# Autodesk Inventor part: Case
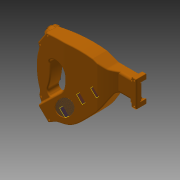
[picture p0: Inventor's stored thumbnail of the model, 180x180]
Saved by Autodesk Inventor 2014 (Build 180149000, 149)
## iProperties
Created: 2008-06
Part Number: Case
Document SubType Name: Modeling
Designer: tangg
Density: 1.06 g/cm^3
Mass: 76.5176 g
Surface Area: 2978.07 cm^2
Volume: 72.1864 cm^3
Stock Number: Case
Material: ABS Plastic
Appearance: Orange
Author: tangg
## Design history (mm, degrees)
sketch "Sketch1"
  geometry: L1 (127.385, 15.24)-(71.466, 15.24); L2 (143.279, 24.13)-(143.279, -44.45); L3 (127.385, -35.56)-(92.277, -35.56); L4 (81.416, -41.677)-(60.325, -76.472); L5 (-66.363, -173.038)-(-82.55, -182.562); L6 (-82.55, -182.562)-(-114.541, -151.565); L7 (47.484, -46.179)-(34.222, -59.441) reference; L8 (47.484, -46.179)-(34.222, -59.441) reference; L9 (34.222, -59.441)-(0, -93.663); L10 (142.009, 25.4)-(133.735, 25.4); L11 (130.56, 22.225)-(130.56, 18.415); L12 (142.009, -45.72)-(133.735, -45.72); L13 (130.56, -42.545)-(130.56, -38.735); L14 (67.2, 15.978)-(37.285, 26.647); L15 (-38.763, -45.049)-(-38.763, -86.032); L16 (-76.383, -122.164)-(-38.763, -86.032); L17 (-122.604, -21.78)-(-95.903, 16.854); A1 r 3.175 centre (133.735, 22.225) between (133.735, 25.4) and (130.56, 22.225); A2 r 3.175 centre (127.385, 18.415) between (127.385, 15.24) and (130.56, 18.415); A3 r 3.175 centre (133.735, -42.545) between (130.56, -42.545) and (133.735, -45.72); A4 r 1.27 centre (142.009, 24.13) between (143.279, 24.13) and (142.009, 25.4); A5 r 1.27 centre (142.009, -44.45) between (142.009, -45.72) and (143.279, -44.45); A6 r 12.7 centre (92.277, -48.26) between (92.277, -35.56) and (81.416, -41.677); A7 r 12.7 centre (71.466, 27.94) between (67.2, 15.978) and (71.466, 15.24); A8 r 3.175 centre (127.385, -38.735) between (130.56, -38.735) and (127.385, -35.56); A9 r 29.205 centre (-63.108, -61.181) between (-38.763, -45.049) and (-81.793, -38.735); 28 further points
  constraints: 34 end point, 18 point on circle, 16 point on line, 16 tangent, 9 centre point, 4 equal radius, 2 horizontal, 40 other
  dimensions: "d25" = 3.175 radius of A1; "d26" = 1.27 radius of A4; "d27" = 12.7 radius of A6; "d137" = 15.24 distance from line of point (0, 0) L1; "d138" = 35.56 distance from line of point (0, 0) L3; "d139" = 25.4 distance from line of point (0, 0) L10; "d140" = 45.72 distance from line of point (0, 0) L12; "d141" = 3.175 radius of A8
extrude "Extrusion8" new body sketch "Sketch1" distance "d71" = 38.1; taper "d72" = 0 deg
feature "Sculpt2"
fillet "Fillet9" dims "d73" = 6.35
sketch "Sketch11"
  geometry: L1 (-127.385, 15.24)-(-71.466, 15.24) reference; L2 (-67.2, 15.978)-(-37.285, 26.647) reference; L3 (114.541, -151.565)-(82.55, -182.562) reference; L4 (82.55, -182.562)-(66.363, -173.038) reference; L5 (-60.325, -76.472)-(-81.416, -41.677) reference; L6 (-92.277, -35.56)-(-127.385, -35.56) reference; L7 (-130.56, -38.735)-(-130.56, -42.545) reference; L8 (-133.735, -45.72)-(-142.009, -45.72) reference; L9 (-143.279, -44.45)-(-143.279, 24.13) reference; L10 (-142.009, 25.4)-(-133.735, 25.4) reference; L11 (-130.56, 22.225)-(-130.56, 18.415) reference; L12 (38.763, -45.049)-(38.763, -86.032) reference; L13 (38.763, -86.032)-(76.383, -122.164) reference; L14 (95.903, 16.854)-(122.604, -21.78) reference; C1 r 2.54 at (-136.949, 19.995); C2 r 2.54 at (-136.949, -39.96); C3 r 2.54 at (92.075, 12.7); C4 r 2.54 at (115.888, -21.78); C5 r 2.54 at (112.713, -141.287); C6 r 2.54 at (80.719, -174.625); A1 r 12.7 centre (-71.466, 27.94) between (-71.466, 15.24) and (-67.2, 15.978) reference; A2 r 12.7 centre (-92.277, -48.26) between (-81.416, -41.677) and (-92.277, -35.56) reference; A3 r 3.175 centre (-133.735, -42.545) between (-133.735, -45.72) and (-130.56, -42.545) reference; A4 r 1.27 centre (-142.009, -44.45) between (-143.279, -44.45) and (-142.009, -45.72) reference; A5 r 1.27 centre (-142.009, 24.13) between (-142.009, 25.4) and (-143.279, 24.13) reference; A6 r 3.175 centre (-133.735, 22.225) between (-130.56, 22.225) and (-133.735, 25.4) reference; A7 r 3.175 centre (-127.385, 18.415) between (-130.56, 18.415) and (-127.385, 15.24) reference; A8 r 3.175 centre (-127.385, -38.735) between (-127.385, -35.56) and (-130.56, -38.735) reference; A9 r 29.205 centre (63.108, -61.181) between (81.793, -38.735) and (38.763, -45.049) reference; 5 further points
  constraints: 6 centre point, 5 equal radius, 9 other
  dimensions: "d60" = 5.08 diameter of C1
  node "Project Cut Edges3"
sketch "Sketch17"
  geometry: L1 (22.589, 40.293)-(146.914, 23.439); 1 further point
  constraints: 2 end point
extrude_surface "ExtrusionSrf4" sketch "Sketch17" dims "d49" = 406.4, "d50" = 0
workplane "Work Plane10"
feature "Sculpt6"
  workplane "Work Plane14"
  workplane "Work Plane15"
extrude "Extrusion21" cut sketch "Sketch11" stored distance "d231" = 25.4; taper "d232" = 0 deg
shell "Shell6" dims "d83" = 2.54
fillet "Fillet21" dims "d147" = 38.1
fillet "Fillet22" dims "d148" = 19.05
workplane "Work Plane17"
sketch "Sketch29" dims "d256" = 31.75, "d257" = 19.05
  geometry: L1 (-12.846, -85.936)-(71.389, -1.701) reference; 2 further points; 1 other entity
  constraints: 2 end point, 1 point on line, 5 other
extrude "Extrusion14" cut sketch "Sketch29" distance "d151" = 1.27; taper "d152" = 0 deg
sketch "Sketch30"
  geometry: L1 (-39.315, 38.1)-(-38.096, 38.1); L2 (-38.096, 38.1)-(-39.315, 38.1); 1 further point
  constraints: 4 end point
fillet "Fillet24" dims "d154" = 4.445
fillet "Fillet25" dims "d155" = 3.2385
fillet "Fillet26" dims "d156" = 3.2385
fillet "Fillet27" dims "d157" = 2
fillet "Fillet28" dims "d158" = 3.2385
fillet "Fillet29" dims "d159" = 3.2385
fillet "Fillet30" dims "d160" = 3.2385
fillet "Fillet31" dims "d161" = 44.45
sketch "Sketch31"
  geometry: L1 (0, 0)-(49.213, 60.325); L2 (49.213, 60.325)-(0, 0); L3 (0, 0)-(39.962, 25.69); L4 (39.962, 25.69)-(55.562, 25.69); L5 (37.557, 46.037)-(46.038, 56.433); L6 (63.5, 48.669)-(62.499, 25.69); L7 (62.499, 25.69)-(39.962, 25.69); L8 (36.513, 44.757)-(46.038, 56.433); L9 (47.372, 58.069)-(34.629, 42.448); L10 (34.629, 42.448)-(39.962, 25.69); L11 (47.372, 58.069)-(58.738, 44.757); L12 (58.738, 44.757)-(55.562, 25.69); 1 further point
  constraints: 24 end point, 3 point on line, 1 collinear
extrude "Extrusion15" cut sketch "Sketch31" distance "d162" = 6.35; taper "d163" = 0 deg
sketch "Sketch26"
  geometry: L1 (165.876, 8.916)-(165.876, -34.925); L2 (0.866, -13.704)-(4.374, -13.704); L3 (4.374, -13.704)-(107.022, 28.87); L4 (107.022, 28.87)-(51.873, 1.085); L5 (51.873, 1.085)-(0.866, -29.735); L6 (0.866, -29.735)-(4.374, -29.735); L7 (4.374, -29.735)-(32.002, -31.726); L8 (32.002, -31.726)-(35.304, -31.726); L9 (0, -2.54)-(55.919, -2.54) reference; L10 (35.108, -48.26)-(0, -48.26) reference; L11 (234.512, -170.453)-(202.008, -139.235) reference; L12 (163.608, -102.355)-(202.008, -139.235) reference; L13 (163.608, -59.541)-(163.608, -102.355) reference; L14 (214.402, -97.907)-(252.068, -97.907); L15 (57.716, -71.396)-(48.141, -55.6) reference; A1 r 31.745 centre (190.493, -76.421) between (206.923, -49.259) and (163.608, -59.541) reference; 33 further points; 2 other entities
  constraints: 18 end point, 2 coincident, 1 horizontal, 1 vertical, 14 other
feature "Rib9" dims "d239" = 3.81, "d240" = 2.54, "d241" = 0
sketch "Sketch54"
  geometry: L1 (-16.193, 56.878)-(15.558, 56.878) reference; L2 (-16.193, 55.291)-(-16.193, 56.878) reference; L3 (-16.193, 55.291)-(15.558, 55.291) reference; L4 (-16.193, 11.703)-(15.558, 11.703) reference; L5 (-16.193, 13.291)-(15.558, 13.291) reference; L6 (-16.193, 11.703)-(-16.193, 13.291) reference; L7 (0, 56.878)-(-16.193, 56.878); L8 (-16.193, 55.291)-(-16.193, 56.878); L9 (-16.193, 55.291)-(-13.7, 55.291); L10 (-13.7, 13.291)-(-16.193, 13.291); L11 (-16.193, 11.703)-(0, 11.703); L12 (0, 56.878)-(0, 11.703); L13 (-12.7, 54.291)-(-12.7, 14.291); L14 (-16.193, 13.291)-(-16.193, 11.703); L15 (0, 68.606)-(0, 24.765) reference; A1 r 1 centre (-13.7, 54.291) between (-12.7, 54.291) and (-13.7, 55.291); A2 r 1 centre (-13.7, 14.291) between (-13.7, 13.291) and (-12.7, 14.291); 3 further points
  constraints: 16 end point, 8 point on line, 4 point on circle, 4 tangent, 2 centre point, 1 collinear
  dimensions: "d265" = 1 radius of A1; "d266" = 12.7 distance between parallel lines of L12 L13; "d267" = 1 radius of A2
extrude "Extrusion24" cut sketch "Sketch54" distance "d268" = 5; taper "d269" = 0 deg
sketch "Sketch32"
  geometry: L1 (41.764, 44.375)-(42.438, 43.477); L2 (43.073, 41.572)-(43.073, 30.162); L3 (46.248, 26.988)-(54.955, 26.988); L4 (54.955, 26.988)-(54.955, 48.055); L5 (54.955, 48.055)-(49.72, 57.478); L6 (41.894, 48.347)-(49.72, 57.478); C1 r 1.588 at (49.212, 51.03); A1 r 3.175 centre (44.304, 46.28) between (41.894, 48.347) and (41.764, 44.375); A2 r 3.175 centre (46.248, 30.162) between (43.073, 30.162) and (46.248, 26.988); A3 r 3.175 centre (39.898, 41.572) between (43.073, 41.572) and (42.438, 43.477); 1 further point
  constraints: 12 end point, 6 point on circle, 6 tangent, 4 centre point
  dimensions: "d164" = 3.175 radius of A1; "d165" = 3.175 radius of A2; "d166" = 3.175 radius of A3
extrude "Extrusion16" join sketch "Sketch32" stored distance "d167" = 7.62; taper "d168" = 0 deg
fillet "Fillet32" dims "d169" = 1.905
shell "Shell7" dims "d170" = 0.0254
sketch "Sketch33"
  geometry: L1 (59.837, 25.958)-(82.078, 25.958); L2 (82.078, 25.958)-(82.078, -25.671); L3 (82.078, -25.671)-(59.837, -25.671); L4 (59.837, -25.671)-(59.837, 25.958); 1 further point
  constraints: 8 end point
extrude "Extrusion17" join sketch "Sketch33" stored distance "d171" = 20.32; taper "d172" = 0 deg
fillet "Fillet33" dims "d173" = 1.905
fillet "Fillet34" dims "d174" = 0.635
sketch "Sketch34"
  geometry: L1 (60.008, 54.61)-(74.93, 54.61); L2 (76.2, 53.34)-(76.2, 31.433); L3 (74.93, 30.162)-(60.008, 30.162); L4 (58.738, 31.433)-(58.738, 53.34); A1 r 1.27 centre (60.008, 53.34) between (60.008, 54.61) and (58.738, 53.34); A2 r 1.27 centre (74.93, 53.34) between (76.2, 53.34) and (74.93, 54.61); A3 r 1.27 centre (74.93, 31.433) between (74.93, 30.162) and (76.2, 31.433); A4 r 1.27 centre (60.008, 31.433) between (58.738, 31.433) and (60.008, 30.162); 5 further points
  constraints: 8 end point, 8 point on circle, 8 point on line, 8 tangent, 4 centre point, 2 equal radius
  dimensions: "d177" = 1.27 radius of A1; "d178" = 1.27 radius of A2
extrude "Extrusion18" join sketch "Sketch34" stored distance "d175" = 12.7; taper "d176" = 0 deg
fillet "Fillet35" dims "d184" = 3.175
sketch "Sketch36"
  geometry: L1 (0, 44.039)-(0, 0) reference; C1 r 3.381 at (0, 22.019); 1 further point
  constraints: 1 centre point, 1 midpoint
extrude "Extrusion20" cut sketch "Sketch36" distance "d185" = 2.54; taper "d186" = 0 deg
sketch "Sketch37"
  geometry: L1 (-111.045, -5.055)-(-107.2, 0.507) reference; L2 (-95.25, -11.861)-(-118.728, 4.365); L3 (-94.025, -10.089)-(-95.25, -11.861); L4 (-95.25, -11.861)-(-118.728, 4.365); L5 (-118.728, 4.365)-(-117.113, 6.701); L6 (-117.113, 6.701)-(-94.025, -10.089); L7 (-108.249, 0.255)-(-99.913, 12.315); L8 (-99.913, 12.315)-(-109.578, 12.47); L9 (-118.728, 4.365)-(-115.166, 9.519); L10 (-109.578, 12.47)-(-112.765, 7.86); L11 (-112.765, 7.86)-(-115.166, 9.519); 2 further points
  constraints: 20 end point, 3 parallel, 2 perpendicular, 2 point on line, 1 midpoint
revolve "Revolution1" sketch "Sketch37" stored, may be unused: angle "d187" = 90 deg
sketch "Sketch40"
  geometry: L1 (-36.223, -87.115)-(-74.624, -123.995) reference; L2 (0, -86.843)-(61.585, -25.258) reference; L3 (-82.286, -169.129)-(-38.592, -125.435) reference; L4 (53.136, -82.662)-(53.136, -82.662); L5 (28.058, -30.048)-(56.795, -58.785); L6 (-5.883, -63.99)-(22.854, -92.726); L7 (-25.456, -146.24)-(-59.397, -112.299); L8 (5.656, -113.712)-(-28.286, -79.771); 8 further points
  constraints: 14 end point, 4 parallel, 3 midpoint, 3 point on line, 2 perpendicular, 10 other
  dimensions: "d246" = 40.64 distance of L5.start L5.end; "d276" = 60 distance from line of L2.start L5; "d277" = 12 distance from line of L2.start L6; "d281" = 48 distance of L7.start L7.end; "d285" = 15 distance from line of L8 L2.start; "d286" = 45 distance from line of L8 point (-42.426, -129.27)
feature "Rib11" dims "d278" = 10, "d279" = 1, "d280" = 0
feature "Rib12" dims "d282" = 3, "d283" = 1, "d284" = 3.5 deg
workplane "Work Plane31"
sketch "Sketch56"
  geometry: C1 r 16.669 at (20.32, 0) reference; 1 further point
extrude "Extrusion26" cut sketch "Sketch56" stored distance "d288" = 12; taper "d289" = 0 deg
workplane "Work Plane30"
sketch "Sketch57"
  geometry: C1 r 16.669 at (20.32, 0) reference; 1 further point
extrude "Extrusion27" cut sketch "Sketch57" stored distance "d291" = 12; taper "d292" = 0 deg
workplane "Work Plane29"
sketch "Sketch58"
  geometry: C1 r 18.503 at (22.998, 0) reference; 1 further point
extrude "Extrusion28" cut sketch "Sketch58" stored distance "d295" = 8; taper "d296" = 0 deg
workplane "Work Plane28"
sketch "Sketch59"
  geometry: C1 r 18.503 at (24, 0) reference; 1 further point
extrude "Extrusion29" cut sketch "Sketch59" stored distance "d298" = 8; taper "d299" = 0 deg
workplane "Work Plane22"
workplane "Work Plane6"
fillet "Fillet36" dims "d205" = 3.175
fillet "Fillet37" dims "d206" = 3.175
sketch "Sketch38"
  geometry: L1 (-109.578, 12.47)-(-99.913, 12.315) reference; L2 (-100.571, 13.095)-(-108.664, 13.225); L3 (-99.913, 12.315)-(-100.571, 13.095); L4 (-108.664, 13.225)-(-109.578, 12.47); 1 further point
  constraints: 6 end point, 1 parallel
revolve "Revolution2" sketch "Sketch38" stored, may be unused: angle "d188" = 90 deg
pattern_circular "Circular Pattern1" dims angle "d190" = 360 deg
sketch "Sketch45"
  geometry: L1 (-0.158, -0.036)-(-10.293, -2.349) reference; L2 (-9.994, -3.661)-(-10.593, -1.038); L3 (-10.593, -1.038)-(-7.562, -0.346); L4 (-7.562, -0.346)-(-6.963, -2.969); L5 (-6.963, -2.969)-(-9.994, -3.661); 2 further points
  constraints: 2 end point, 1 midpoint, 1 parallel, 3 other
  dimensions: "d210" = 3.10847 distance of L2.end L3.end; "d211" = 2.69065 distance of L2.start L2.end
emboss "Emboss2" sketch "Sketch45" dims "d60" = 5.08, "d212" = 0.254, "d213" = 0
sketch "Sketch46"
  geometry: L1 (-9.28, 7.401)-(0, 0) reference; L2 (-9.118, 5.809)-(-7.692, 7.597); L3 (-7.692, 7.597)-(-5.259, 5.656); L4 (-5.259, 5.656)-(-6.685, 3.868); L5 (-6.685, 3.868)-(-9.118, 5.809); 2 further points
  constraints: 2 end point, 1 midpoint, 1 parallel, 1 point on line, 3 other
  dimensions: "d215" = 3.11222 distance of L2.end L3.end; "d216" = 2.28723 distance of L2.start L2.end
emboss "Emboss3" sketch "Sketch46" dims "d60" = 5.08, "d217" = 0.254, "d218" = 0
sketch "Sketch47"
  geometry: L1 (0, 11.87)-(0, 0) reference; L2 (-1.144, 10.764)-(1.144, 10.764); L3 (1.144, 10.764)-(1.144, 7.587); L4 (1.144, 7.587)-(-1.144, 7.587); L5 (-1.144, 7.587)-(-1.144, 10.764); 2 further points
  constraints: 2 end point, 1 midpoint, 1 parallel, 1 point on line, 1 vertical, 2 other
  dimensions: "d219" = 3.17644 distance of L2.end L3.end; "d220" = 2.28723 distance of L2.start L2.end
emboss "Emboss4" sketch "Sketch47" dims "d60" = 5.08, "d221" = 0.254, "d222" = 0
sketch "Sketch48"
  geometry: L1 (9.28, 7.401)-(0, 0) reference; L2 (7.652, 7.565)-(9.078, 5.777); L3 (9.078, 5.777)-(6.695, 3.877); L4 (6.695, 3.877)-(5.269, 5.665); L5 (5.269, 5.665)-(7.652, 7.565); 2 further points
  constraints: 2 end point, 1 midpoint, 1 parallel, 1 point on line, 3 other
  dimensions: "d223" = 3.048 distance of L2.end L3.end; "d224" = 2.28723 distance of L3.end L4.end
emboss "Emboss5" sketch "Sketch48" dims "d60" = 5.08, "d225" = 0.254, "d226" = 0
sketch "Sketch49"
  geometry: L1 (11.572, -2.641)-(1.409, -0.322); L2 (10.47, -1.217)-(9.962, -3.447); L3 (9.962, -3.447)-(6.927, -2.754); L4 (6.927, -2.754)-(7.436, -0.524); L5 (7.436, -0.524)-(10.47, -1.217); L6 (11.572, -2.641)-(0, 0) reference; 2 further points
  constraints: 4 end point, 2 parallel, 1 midpoint, 1 point on line, 3 other
  dimensions: "d227" = 3.11222 distance of L2.end L3.end; "d228" = 2.28723 distance of L3.end L4.end
emboss "Emboss6" sketch "Sketch49" dims "d60" = 5.08, "d229" = 0.254, "d230" = 0
sketch "Sketch50"
  geometry: 1 further point
sketch "Sketch51"
  geometry: 1 further point
fillet "Fillet39" dims "d259" = 0.3175
sketch "Sketch55"
  geometry: L1 (12.7, 6.985)-(25.4, 6.985) reference; L2 (25.4, 6.985)-(25.4, 19.685) reference; L3 (-12.7, 6.985)-(12.7, 6.985) reference; L4 (25.4, 19.685)-(12.7, 19.685) reference; L5 (0, 6.985)-(25.4, 6.985); L6 (25.4, 19.685)-(12.7, 19.685); L7 (12.7, 19.685)-(12.7, 26.575); L8 (10.7, 28.575)-(0, 28.575); L9 (0, 28.575)-(0, 6.985); A1 r 2 centre (10.7, 26.575) between (12.7, 26.575) and (10.7, 28.575)
  constraints: 11 end point, 2 point on circle, 2 tangent, 1 centre point, 1 midpoint
  dimensions: "d275" = 2 radius of A1
extrude "Extrusion25" cut sketch "Sketch55" distance "d272" = 5; taper "d273" = 0 deg
body "Solid1"
sketch "Sketch13"
  geometry: L1 (-125.797, 22.007)-(-90.487, 22.007); L2 (-125.797, 22.007)-(-127.827, 26.574); L3 (-127.385, 0)-(-93.42, 0) reference; L4 (-127.827, 26.574)-(-152.402, 26.574); 5 further points
  constraints: 6 end point, 2 horizontal, 3 other
body "Srf1"
body "Srf2"
node "Reference4"
node "Reference5"
node "Reference6"
node "Reference7"
node "Reference8"
node "Reference9"
node "Reference10"
node "Reference11"
node "Reference12"
node "Reference13"
node "Reference18"
node "Reference19"
extrude_surface "ExtrusionSrf3" dims "d39" = 304.8, "d40" = 0
other parameters: "d16" = 38.1, "d75" = 0, "d76" = 0, "d119" = 38.1
